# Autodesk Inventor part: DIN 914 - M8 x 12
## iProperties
Created: 2006-02
Part Number: DIN 914 - M8 x 12
Material: Steel, Mild
Description: Hexagon Socket Set Screw
Document SubType Name: Modeling
Standard: DIN 914
Designer: Andy Moles
Standards Organization: DIN
Language: en-US
Size Designation: M8 x 12
Categories: <MemberInstance><Categories><Category DisplayName="Fasteners" InternalName="e4da775c-781d-43d5-af7c-5136215cf5a6" Mnemonic="FSTN"><Category DisplayName="Bolts"
Mass: 4.20865 g
Surface Area: 4.57509 cm^2
Volume: 0.535451 cm^3
Density: 7.86 g/cm^3
Author: Andy Moles
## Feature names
1. Body [Revolution]
2. Slot [Extrusion]
3. Chamfer1
4. Chamfer2
